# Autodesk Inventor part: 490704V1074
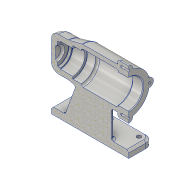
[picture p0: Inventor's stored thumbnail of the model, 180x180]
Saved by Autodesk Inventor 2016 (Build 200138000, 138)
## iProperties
Created: 2019-07
Part Number: 490704V1074
Material: 알루미늄 6061
Document SubType Name: Modeling
Designer: 605-12
Density: 2.7 g/cm^3
Appearance: 알루미늄 - 평지
Mass: 644.067 g
Surface Area: 654.969 cm^2
Volume: 238.543 cm^3
Author: 605-12
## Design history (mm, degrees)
sketch "스케치1"
  geometry: L1 (-56, 0)-(56, 0); L2 (41, 21)-(56, 21); L3 (41, 21)-(41, 24); L4 (41, 24)-(-13, 24); L5 (-13, 24)-(-13, 21); L6 (-13, 21)-(-25, 21); L7 (-25, 21)-(-25, 17.5); L8 (-25, 17.5)-(-43, 17.5); L9 (-43, 17.5)-(-43, 16); L10 (-43, 16)-(-47, 16); L11 (-47, 16)-(-47, 10.5); L12 (-47, 10.5)-(-50, 10.5); L13 (-50, 10.5)-(-50, 0); L14 (56, 21)-(56, 30); L15 (56, 30)-(-11, 30); L16 (-11, 30)-(-31, 25); L17 (-31, 25)-(-56, 25); L18 (-56, 25)-(-56, 0); 1 further point
  constraints: 36 end point, 7 vertical, 5 perpendicular, 3 parallel, 2 horizontal, 1 midpoint, 1 point on line, 1 vertical alignment
  dimensions: "d0" = 112 distance of L1.start L1.end; "d1" = 56 distance of point (0, 0) L1.start; "d2" = 42 diameter of L2 L1; "d3" = 15 distance of L2.start L2.end; "d4" = 54 distance of L3.end L4.end; "d5" = 48 diameter of L4 L1; "d6" = 42 diameter of L6 L1; "d7" = 12 distance of L5.end L6.end; "d8" = 18 distance of L7.end L8.end; "d9" = 35 diameter of L8 L1; "d10" = 32 diameter of L10 L1; "d11" = 4 distance of L9.end L10.end; "d12" = 3 distance of L11.end L12.end; "d13" = 21 diameter of L12 L1; "d15" = 45 distance from line of L15.end L18; "d16" = 25 distance of L16.end L17.end; "d17" = 60 diameter of L15 L1; "d18" = 50 diameter of L17 L1
revolve "회전1" sketch "스케치1" stored, may be unused: angle "d19" = 90 deg
sketch "스케치2"
  geometry: L1 (-56, -70)-(56, -70); L2 (56, -70)-(56, -80); L3 (56, -80)-(-56, -80); L4 (-56, -80)-(-56, -70); 1 further point
  constraints: 8 end point, 2 parallel, 1 horizontal, 1 perpendicular
  dimensions: "d20" = 80 distance from line of point (0, 0) L3; "d21" = 112 distance of L2.end L3.end; "d22" = 10 distance of L3.end L1.start; "d23" = 56 distance from line of point (0, 0) L4
extrude "돌출1" join sketch "스케치2" stored distance "d24" = 70; taper "d25" = 0 deg
sketch "스케치3"
  geometry: L1 (-70, -35)-(-70, 35) reference; L2 (-22.666, 19.654)-(-70, 28); L3 (-22.666, -19.654)-(-70, -28); L4 (-70, 35)-(-80, 35) reference; L5 (-80, -35)-(-70, -35) reference; A1 r 30 centre (0, 0) between (-22.666, 19.654) and (-22.666, -19.654) reference; 1 further point
  constraints: 4 end point, 2 point on circle, 2 point on line
  dimensions: "d26" = 100 deg angle of L2 L1; "d27" = 7 distance from line of L2.end L4; "d28" = 7 distance from line of L5 L3.end; "d29" = 100 deg angle of L1 L3
extrude "돌출2" join sketch "스케치3" stored distance "d30" = 8; taper "d31" = 0 deg
sketch "스케치4"
  geometry: L1 (-11, -30)-(56, -30) reference; L2 (-56, -70)-(56, -70) reference; L3 (31, -30)-(31, -34.292); L4 (31, -34.292)-(31, -70); L5 (56, -70)-(56, -80) reference; 1 further point
  constraints: 4 end point, 3 point on line, 1 perpendicular
  dimensions: "d32" = 25 distance between parallel lines of L5 L4
feature "리브1" sketch "스케치4" dims "d33" = 1, "d34" = 8, "d35" = 0, "d36" = 0, "d37" = 1, "d38" = 1
sketch "스케치5"
  geometry: L1 (-31, -25)-(-11, -30) reference; L2 (-56, -70)-(56, -70) reference; L3 (-11, -30)-(56, -30) reference; L4 (-20.57, -27.607)-(-36, -70); L5 (-56, -80)-(-56, -70) reference; 1 further point
  constraints: 2 end point, 2 point on line
  dimensions: "d39" = 20 distance from line of L5 L4.end; "d40" = 110 deg angle of L2 L4
feature "리브2" sketch "스케치5" dims "d41" = 1, "d42" = 8, "d43" = 0, "d44" = 0, "d45" = 1, "d46" = 1
fillet "모깎기1" dims "d47" = 10
sketch "스케치7"
  geometry: L1 (92, 70)-(0, 70) reference; L2 (102, 10)-(102, 60) reference; L3 (0, 0)-(92, 0) reference; L4 (-10, 10)-(-10, 60) reference; A1 r 10 centre (0, 60) between (0, 70) and (-10, 60) reference; A2 r 10 centre (92, 60) between (102, 60) and (92, 70) reference; A3 r 10 centre (92, 10) between (92, 0) and (102, 10) reference; A4 r 10 centre (0, 10) between (-10, 10) and (0, 0) reference; 1 further point
hole "구멍1" sketch "스케치7" at (0, 10), (0, 60), (92, 60), (92, 10) diameter "d48" = 6; stored, may be unused: countersink angle "d52" = 90 deg, drill point angle "d54" = 118 deg; dims "d49" = 6, "d50" = 4, "d51" = 2, "d53" = 8
sketch "스케치8"
  geometry: C1 r 21 at (0, 0) reference; A1 r 30 centre (0, 0) between (4, -29.732) and (-4, -29.732) reference; A2 r 30 centre (0, 0) between (4, -29.732) and (-4, -29.732) reference; A3 r 6 centre (0, 30) between (5.97, 29.4) and (-5.97, 29.4); A4 r 6 centre (0, 30) between (-5.97, 29.4) and (5.97, 29.4); 2 further points
  constraints: 7 point on circle, 2 centre point, 2 vertical alignment, 1 other
  dimensions: "d58" = 6 radius of A3
extrude "돌출3" join sketch "스케치8" distance "d59" = 16; taper "d60" = 0 deg
fillet "모깎기2" dims "d61" = 3
fillet "모깎기3" dims "d62" = 1
hole "구멍2" diameter "d65" = 3.242; stored, may be unused: countersink angle "d69" = 90 deg, drill point angle "d71" = 120 deg; dims "d63" = 10, "d64" = 10, "d66" = 8, "d67" = 4, "d68" = 2, "d70" = 11
node "작업 평면1"
sketch "스케치9"
  geometry: L1 (33.5, 30.171)-(33.5, 36) reference; 2 further points
  constraints: 1 horizontal alignment, 1 other
  dimensions: "d75" = 42 distance from line of L1 point (-8.5, 0)
feature "엠보싱1" sketch "스케치9" dims "d19" = 90 deg, "d76" = 0.5, "d77" = 0
fillet "모깎기4" dims "d78" = 10
fillet "모깎기6" dims "d80" = 3
fillet "모깎기7" dims "d81" = 3
fillet "모깎기8" dims "d82" = 3
fillet "모깎기9" dims "d83" = 3
chamfer "모따기1" distance "d84" = 1; stored, may be unused: second distance "d85" = 2, angle "d86" = 45 deg
fillet "모깎기10" dims "d87" = 0.3
fillet "모깎기11" dims "d88" = 3
chamfer "모따기2" distance "d89" = 3; stored, may be unused: second distance "d90" = 2, angle "d91" = 45 deg
fillet "모깎기12" dims "d92" = 3
node "솔리드1"
pattern_circular "원형 패턴1" dims "d73" = 360 deg
node "투영된 루프1"
node "투영된 루프2"
